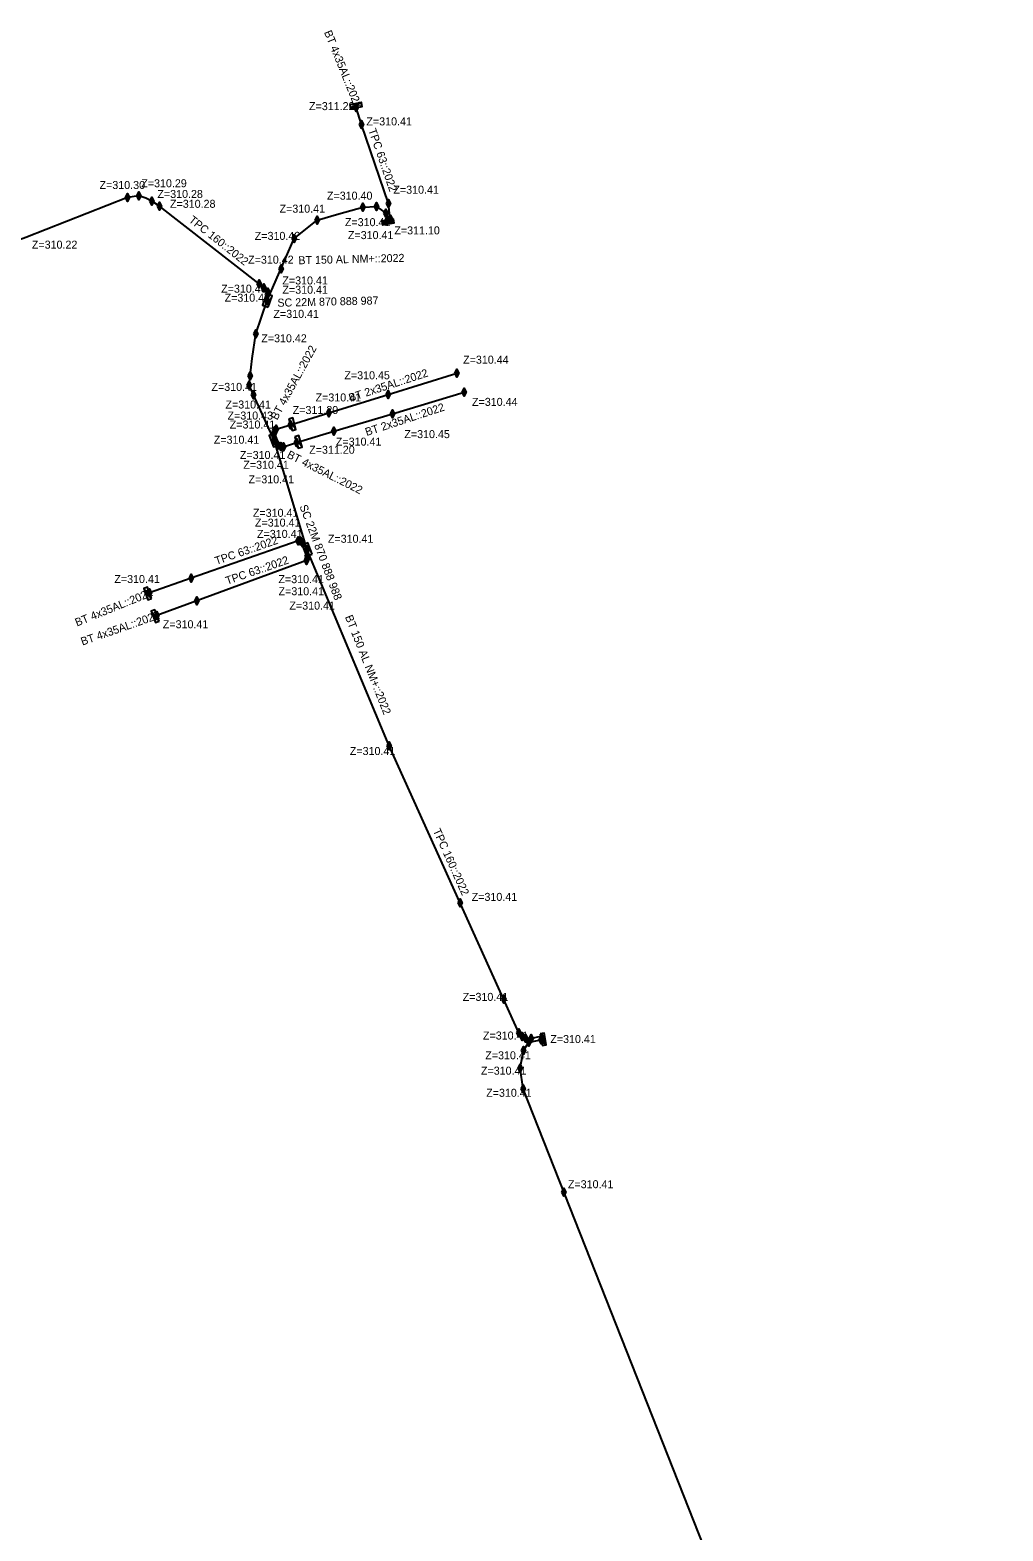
# Model space of a CAD drawing. Extents: x 799271 to 799523, y 67737 to 68184.
# Drawn here: x 799313.8 to 799362.5, y 68072.4 to 68147.5 of the extents above; entities that cross this region are included whole.
import ezdxf

# ---------------------------------------------------------------- set-up
doc = ezdxf.new("R2010")
doc.units = 0
for name, color, linetype in [('PGOC_BRCHT_DI_CONSTRUIT', 7, 'Continuous'), ('PGOC_BRCHT_LR_CONSTRUIT', 7, 'Continuous'), ('PGOC_BT_CONSTRUIT', 7, 'Continuous'), ('PGOC_PROTECTION_MECANIQUE', 7, 'Continuous'), ('PGOC_PTRL', 7, 'Continuous')]:
    doc.layers.add(name, color=color, linetype=linetype)

msp = doc.modelspace()

# ---------------------------------------------------------------- linework, layer by layer
at = {"layer": 'PGOC_BRCHT_DI_CONSTRUIT'}
for points in [[(799326.854, 68127.723), (799328.779, 68128.318), (799331.743, 68129.241), (799335.179, 68130.296)], [(799327.159, 68126.839), (799329.027, 68127.398), (799331.95, 68128.272), (799335.54, 68129.356)]]:
    msp.add_lwpolyline(points, dxfattribs=at)
at = {"layer": 'PGOC_BRCHT_LR_CONSTRUIT'}
for p, q in [((799330.406, 68143.831), (799329.852, 68143.524)), ((799327.127, 68127.487), (799326.774, 68128.012)), ((799327.432, 68126.604), (799327.078, 68127.128)), ((799319.514, 68119.534), (799319.912, 68119.042)), ((799319.886, 68118.399), (799320.284, 68117.908))]:
    msp.add_line(p, q, dxfattribs=at)
for points in [[(799329.852, 68143.524), (799330.442, 68143.634), (799330.406, 68143.831), (799329.816, 68143.721)], [(799326.774, 68128.012), (799326.935, 68127.434), (799327.127, 68127.487), (799326.966, 68128.065)], [(799326.285, 68126.724), (799326.074, 68127.286), (799325.793, 68127.18), (799326.004, 68126.619)], [(799327.078, 68127.128), (799327.24, 68126.55), (799327.432, 68126.604), (799327.271, 68127.182)], [(799327.934, 68121.252), (799327.723, 68121.814), (799327.442, 68121.709), (799327.653, 68121.147)], [(799319.912, 68119.042), (799319.701, 68119.604), (799319.514, 68119.534), (799319.725, 68118.972)], [(799320.284, 68117.908), (799320.073, 68118.47), (799319.886, 68118.399), (799320.097, 68117.838)]]:
    msp.add_lwpolyline(points, close=True, dxfattribs=at)
for points in [[(799331.841, 68137.991), (799331.755, 68138.791), (799330.407, 68142.737), (799330.147, 68143.579)], [(799326.041, 68126.947), (799326.038, 68127.28), (799326.064, 68127.423), (799326.142, 68127.5), (799326.854, 68127.723)], [(799326.041, 68126.947), (799326.228, 68126.708), (799326.37, 68126.638), (799326.503, 68126.627), (799327.159, 68126.839)], [(799327.69, 68121.475), (799327.457, 68121.825), (799327.332, 68121.914), (799327.237, 68121.913), (799326.855, 68121.78), (799321.897, 68120.052), (799319.807, 68119.323)], [(799327.69, 68121.475), (799327.693, 68121.162), (799327.695, 68121.014), (799327.658, 68120.945), (799322.168, 68118.923), (799320.179, 68118.189)]]:
    msp.add_lwpolyline(points, dxfattribs=at)
at = {"layer": 'PGOC_BT_CONSTRUIT'}
for points in [[(799325.695, 68133.935), (799325.714, 68134.244), (799325.72, 68134.356), (799325.523, 68134.562), (799325.287, 68134.766), (799320.298, 68138.654), (799319.918, 68138.897), (799319.629, 68139.051), (799319.267, 68139.164), (799318.707, 68139.081), (799313.619, 68137.078), (799309.462, 68135.566), (799303.767, 68133.234), (799297.376, 68130.329), (799292.64, 68128.222), (799285.412, 68124.768), (799279.22, 68121.838), (799276.144, 68120.348), (799271.55, 68118.005), (799271.55, 68118.005), (799271.55, 68118.005)], [(799339.366, 68097.137), (799338.895, 68097.044), (799338.6, 68097.061), (799338.444, 68097.136), (799338.277, 68097.326), (799331.797, 68111.675), (799327.69, 68121.475), (799326.041, 68126.947), (799325.012, 68129.216), (799324.793, 68129.699), (799324.844, 68130.165), (799324.94, 68131.043), (799325.13, 68132.267), (799325.695, 68133.935), (799327.046, 68137.031), (799328.195, 68137.96), (799329.277, 68138.271), (799330.475, 68138.607), (799331.153, 68138.638), (799331.618, 68138.305), (799331.714, 68137.967)], [(799331.477, 68137.821), (799331.988, 68137.916)], [(799331.521, 68137.91), (799331.55, 68137.753)], [(799331.619, 68137.929), (799331.649, 68137.771)], [(799331.717, 68137.947), (799331.747, 68137.79)], [(799331.816, 68137.965), (799331.845, 68137.808)], [(799331.914, 68137.984), (799331.943, 68137.826)], [(799362.485, 68037.029), (799361.95, 68037.023), (799361.114, 68037.015), (799360.807, 68037.092), (799360.472, 68037.497), (799357.336, 68045.17), (799355.021, 68050.739), (799353.254, 68056.515), (799351.046, 68062.246), (799349.101, 68067.639), (799338.488, 68094.517), (799338.336, 68095.563), (799338.503, 68096.44), (799338.776, 68096.853), (799339.395, 68096.978)], [(799339.378, 68097.178), (799339.536, 68097.207)], [(799339.397, 68097.08), (799339.554, 68097.109)], [(799339.415, 68096.981), (799339.572, 68097.011)], [(799339.541, 68096.74), (799339.446, 68097.252)], [(799339.433, 68096.883), (799339.591, 68096.912)], [(799339.452, 68096.785), (799339.609, 68096.814)]]:
    msp.add_lwpolyline(points, dxfattribs=at)
for points in [[(799332.009, 68138.022), (799331.419, 68137.911), (799331.456, 68137.715), (799332.045, 68137.825)], [(799325.738, 68133.608), (799325.938, 68134.174), (799325.655, 68134.274), (799325.455, 68133.708)], [(799339.34, 68097.273), (799339.45, 68096.683), (799339.647, 68096.719), (799339.537, 68097.309)]]:
    msp.add_lwpolyline(points, close=True, dxfattribs=at)
at = {"layer": 'PGOC_PTRL'}
for points in [[(799330.047, 68143.579), (799330.147, 68143.779), (799330.247, 68143.579), (799330.147, 68143.379), (799330.047, 68143.579)], [(799330.247, 68143.579), (799330.147, 68143.579), (799330.047, 68143.579)], [(799330.147, 68143.779), (799330.147, 68143.379)], [(799330.307, 68142.737), (799330.407, 68142.937), (799330.507, 68142.737), (799330.407, 68142.537), (799330.307, 68142.737)], [(799330.507, 68142.737), (799330.407, 68142.737), (799330.307, 68142.737)], [(799330.407, 68142.937), (799330.407, 68142.537)], [(799318.607, 68139.081), (799318.707, 68139.281), (799318.807, 68139.081), (799318.707, 68138.881), (799318.607, 68139.081)], [(799318.807, 68139.081), (799318.707, 68139.081), (799318.607, 68139.081)], [(799318.707, 68139.281), (799318.707, 68138.881)], [(799319.167, 68139.164), (799319.267, 68139.364), (799319.367, 68139.164), (799319.267, 68138.964), (799319.167, 68139.164)], [(799319.367, 68139.164), (799319.267, 68139.164), (799319.167, 68139.164)], [(799319.267, 68139.364), (799319.267, 68138.964)], [(799319.818, 68138.897), (799319.918, 68139.097), (799320.018, 68138.897), (799319.918, 68138.697), (799319.818, 68138.897)], [(799319.918, 68139.097), (799319.918, 68138.697)], [(799331.655, 68138.791), (799331.755, 68138.991), (799331.855, 68138.791), (799331.755, 68138.591), (799331.655, 68138.791)], [(799331.755, 68138.991), (799331.755, 68138.591)], [(799320.018, 68138.897), (799319.918, 68138.897), (799319.818, 68138.897)], [(799320.198, 68138.654), (799320.298, 68138.854), (799320.398, 68138.654), (799320.298, 68138.454), (799320.198, 68138.654)], [(799320.398, 68138.654), (799320.298, 68138.654), (799320.198, 68138.654)], [(799320.298, 68138.854), (799320.298, 68138.454)], [(799330.375, 68138.607), (799330.475, 68138.807), (799330.575, 68138.607), (799330.475, 68138.407), (799330.375, 68138.607)], [(799330.575, 68138.607), (799330.475, 68138.607), (799330.375, 68138.607)], [(799330.475, 68138.807), (799330.475, 68138.407)], [(799331.053, 68138.638), (799331.153, 68138.838), (799331.253, 68138.638), (799331.153, 68138.438), (799331.053, 68138.638)], [(799331.253, 68138.638), (799331.153, 68138.638), (799331.053, 68138.638)], [(799331.153, 68138.838), (799331.153, 68138.438)], [(799331.518, 68138.305), (799331.618, 68138.505), (799331.718, 68138.305), (799331.618, 68138.105), (799331.518, 68138.305)], [(799331.718, 68138.305), (799331.618, 68138.305), (799331.518, 68138.305)], [(799331.618, 68138.505), (799331.618, 68138.105)], [(799331.855, 68138.791), (799331.755, 68138.791), (799331.655, 68138.791)], [(799328.095, 68137.96), (799328.195, 68138.16), (799328.295, 68137.96), (799328.195, 68137.76), (799328.095, 68137.96)], [(799328.295, 68137.96), (799328.195, 68137.96), (799328.095, 68137.96)], [(799328.195, 68138.16), (799328.195, 68137.76)], [(799331.614, 68137.967), (799331.714, 68138.167), (799331.814, 68137.967), (799331.714, 68137.767), (799331.614, 68137.967)], [(799331.814, 68137.967), (799331.714, 68137.967), (799331.614, 68137.967)], [(799331.714, 68138.167), (799331.714, 68137.767)], [(799331.749, 68137.999), (799331.849, 68138.199), (799331.949, 68137.999), (799331.849, 68137.799), (799331.749, 68137.999)], [(799331.949, 68137.999), (799331.849, 68137.999), (799331.749, 68137.999)], [(799331.849, 68138.199), (799331.849, 68137.799)], [(799326.946, 68137.031), (799327.046, 68137.231), (799327.146, 68137.031), (799327.046, 68136.831), (799326.946, 68137.031)], [(799327.146, 68137.031), (799327.046, 68137.031), (799326.946, 68137.031)], [(799327.046, 68137.231), (799327.046, 68136.831)], [(799326.287, 68135.522), (799326.387, 68135.722), (799326.487, 68135.522), (799326.387, 68135.322), (799326.287, 68135.522)], [(799326.487, 68135.522), (799326.387, 68135.522), (799326.287, 68135.522)], [(799326.387, 68135.722), (799326.387, 68135.322)], [(799325.187, 68134.766), (799325.287, 68134.966), (799325.387, 68134.766), (799325.287, 68134.566), (799325.187, 68134.766)], [(799325.387, 68134.766), (799325.287, 68134.766), (799325.187, 68134.766)], [(799325.287, 68134.966), (799325.287, 68134.566)], [(799325.423, 68134.562), (799325.523, 68134.762), (799325.623, 68134.562), (799325.523, 68134.362), (799325.423, 68134.562)], [(799325.623, 68134.562), (799325.523, 68134.562), (799325.423, 68134.562)], [(799325.523, 68134.762), (799325.523, 68134.362)], [(799325.62, 68134.356), (799325.72, 68134.556), (799325.82, 68134.356), (799325.72, 68134.156), (799325.62, 68134.356)], [(799325.72, 68134.556), (799325.72, 68134.156)], [(799325.595, 68133.935), (799325.695, 68134.135), (799325.795, 68133.935), (799325.695, 68133.735), (799325.595, 68133.935)], [(799325.795, 68133.935), (799325.695, 68133.935), (799325.595, 68133.935)], [(799325.614, 68134.244), (799325.714, 68134.444), (799325.814, 68134.244), (799325.714, 68134.044), (799325.614, 68134.244)], [(799325.814, 68134.244), (799325.714, 68134.244), (799325.614, 68134.244)], [(799325.82, 68134.356), (799325.72, 68134.356), (799325.62, 68134.356)], [(799325.695, 68134.135), (799325.695, 68133.735)], [(799325.714, 68134.444), (799325.714, 68134.044)], [(799325.03, 68132.267), (799325.13, 68132.467), (799325.23, 68132.267), (799325.13, 68132.067), (799325.03, 68132.267)], [(799325.23, 68132.267), (799325.13, 68132.267), (799325.03, 68132.267)], [(799325.13, 68132.467), (799325.13, 68132.067)], [(799324.744, 68130.165), (799324.844, 68130.365), (799324.944, 68130.165), (799324.844, 68129.965), (799324.744, 68130.165)], [(799324.944, 68130.165), (799324.844, 68130.165), (799324.744, 68130.165)], [(799324.844, 68130.365), (799324.844, 68129.965)], [(799335.079, 68130.296), (799335.179, 68130.496), (799335.279, 68130.296), (799335.179, 68130.096), (799335.079, 68130.296)], [(799335.279, 68130.296), (799335.179, 68130.296), (799335.079, 68130.296)], [(799335.179, 68130.496), (799335.179, 68130.096)], [(799324.693, 68129.699), (799324.793, 68129.899), (799324.893, 68129.699), (799324.793, 68129.499), (799324.693, 68129.699)], [(799324.893, 68129.699), (799324.793, 68129.699), (799324.693, 68129.699)], [(799324.793, 68129.899), (799324.793, 68129.499)], [(799324.912, 68129.216), (799325.012, 68129.416), (799325.112, 68129.216), (799325.012, 68129.016), (799324.912, 68129.216)], [(799325.112, 68129.216), (799325.012, 68129.216), (799324.912, 68129.216)], [(799325.012, 68129.416), (799325.012, 68129.016)], [(799331.643, 68129.241), (799331.743, 68129.441), (799331.843, 68129.241), (799331.743, 68129.041), (799331.643, 68129.241)], [(799331.843, 68129.241), (799331.743, 68129.241), (799331.643, 68129.241)], [(799331.743, 68129.441), (799331.743, 68129.041)], [(799335.44, 68129.356), (799335.54, 68129.556), (799335.64, 68129.356), (799335.54, 68129.156), (799335.44, 68129.356)], [(799335.64, 68129.356), (799335.54, 68129.356), (799335.44, 68129.356)], [(799335.54, 68129.556), (799335.54, 68129.156)], [(799328.679, 68128.318), (799328.779, 68128.518), (799328.879, 68128.318), (799328.779, 68128.118), (799328.679, 68128.318)], [(799328.779, 68128.518), (799328.779, 68128.118)], [(799331.85, 68128.272), (799331.95, 68128.472), (799332.05, 68128.272), (799331.95, 68128.072), (799331.85, 68128.272)], [(799331.95, 68128.472), (799331.95, 68128.072)], [(799326.042, 68127.5), (799326.142, 68127.7), (799326.242, 68127.5), (799326.142, 68127.3), (799326.042, 68127.5)], [(799326.142, 68127.7), (799326.142, 68127.3)], [(799326.754, 68127.723), (799326.854, 68127.923), (799326.954, 68127.723), (799326.854, 68127.523), (799326.754, 68127.723)], [(799326.954, 68127.723), (799326.854, 68127.723), (799326.754, 68127.723)], [(799326.854, 68127.923), (799326.854, 68127.523)], [(799328.879, 68128.318), (799328.779, 68128.318), (799328.679, 68128.318)], [(799332.05, 68128.272), (799331.95, 68128.272), (799331.85, 68128.272)], [(799325.938, 68127.28), (799326.038, 68127.48), (799326.138, 68127.28), (799326.038, 68127.08), (799325.938, 68127.28)], [(799326.138, 68127.28), (799326.038, 68127.28), (799325.938, 68127.28)], [(799325.941, 68126.947), (799326.041, 68127.147), (799326.141, 68126.947), (799326.041, 68126.747), (799325.941, 68126.947)], [(799325.964, 68127.423), (799326.064, 68127.623), (799326.164, 68127.423), (799326.064, 68127.223), (799325.964, 68127.423)], [(799326.164, 68127.423), (799326.064, 68127.423), (799325.964, 68127.423)], [(799326.038, 68127.48), (799326.038, 68127.08)], [(799326.041, 68127.147), (799326.041, 68126.747)], [(799326.242, 68127.5), (799326.142, 68127.5), (799326.042, 68127.5)], [(799326.064, 68127.623), (799326.064, 68127.223)], [(799327.059, 68126.839), (799327.159, 68127.039), (799327.259, 68126.839), (799327.159, 68126.639), (799327.059, 68126.839)], [(799327.159, 68127.039), (799327.159, 68126.639)], [(799328.927, 68127.398), (799329.027, 68127.598), (799329.127, 68127.398), (799329.027, 68127.198), (799328.927, 68127.398)], [(799329.127, 68127.398), (799329.027, 68127.398), (799328.927, 68127.398)], [(799329.027, 68127.598), (799329.027, 68127.198)], [(799326.141, 68126.947), (799326.041, 68126.947), (799325.941, 68126.947)], [(799326.128, 68126.708), (799326.228, 68126.908), (799326.328, 68126.708), (799326.228, 68126.508), (799326.128, 68126.708)], [(799326.328, 68126.708), (799326.228, 68126.708), (799326.128, 68126.708)], [(799326.228, 68126.908), (799326.228, 68126.508)], [(799326.27, 68126.638), (799326.37, 68126.838), (799326.47, 68126.638), (799326.37, 68126.438), (799326.27, 68126.638)], [(799326.47, 68126.638), (799326.37, 68126.638), (799326.27, 68126.638)], [(799326.37, 68126.838), (799326.37, 68126.438)], [(799326.403, 68126.627), (799326.503, 68126.827), (799326.603, 68126.627), (799326.503, 68126.427), (799326.403, 68126.627)], [(799326.603, 68126.627), (799326.503, 68126.627), (799326.403, 68126.627)], [(799326.503, 68126.827), (799326.503, 68126.427)], [(799327.259, 68126.839), (799327.159, 68126.839), (799327.059, 68126.839)], [(799327.137, 68121.913), (799327.237, 68122.113), (799327.337, 68121.913), (799327.237, 68121.713), (799327.137, 68121.913)], [(799327.337, 68121.913), (799327.237, 68121.913), (799327.137, 68121.913)], [(799327.232, 68121.914), (799327.332, 68122.114), (799327.432, 68121.914), (799327.332, 68121.714), (799327.232, 68121.914)], [(799327.432, 68121.914), (799327.332, 68121.914), (799327.232, 68121.914)], [(799327.237, 68122.113), (799327.237, 68121.713)], [(799327.332, 68122.114), (799327.332, 68121.714)], [(799327.357, 68121.825), (799327.457, 68122.025), (799327.557, 68121.825), (799327.457, 68121.625), (799327.357, 68121.825)], [(799327.557, 68121.825), (799327.457, 68121.825), (799327.357, 68121.825)], [(799327.457, 68122.025), (799327.457, 68121.625)], [(799327.558, 68120.945), (799327.658, 68121.145), (799327.758, 68120.945), (799327.658, 68120.745), (799327.558, 68120.945)], [(799327.59, 68121.475), (799327.69, 68121.675), (799327.79, 68121.475), (799327.69, 68121.275), (799327.59, 68121.475)], [(799327.79, 68121.475), (799327.69, 68121.475), (799327.59, 68121.475)], [(799327.593, 68121.162), (799327.693, 68121.362), (799327.793, 68121.162), (799327.693, 68120.962), (799327.593, 68121.162)], [(799327.793, 68121.162), (799327.693, 68121.162), (799327.593, 68121.162)], [(799327.595, 68121.014), (799327.695, 68121.214), (799327.795, 68121.014), (799327.695, 68120.814), (799327.595, 68121.014)], [(799327.795, 68121.014), (799327.695, 68121.014), (799327.595, 68121.014)], [(799327.658, 68121.145), (799327.658, 68120.745)], [(799327.69, 68121.675), (799327.69, 68121.275)], [(799327.693, 68121.362), (799327.693, 68120.962)], [(799327.695, 68121.214), (799327.695, 68120.814)], [(799321.797, 68120.052), (799321.897, 68120.252), (799321.997, 68120.052), (799321.897, 68119.852), (799321.797, 68120.052)], [(799321.897, 68120.252), (799321.897, 68119.852)], [(799327.758, 68120.945), (799327.658, 68120.945), (799327.558, 68120.945)], [(799319.707, 68119.323), (799319.807, 68119.523), (799319.907, 68119.323), (799319.807, 68119.123), (799319.707, 68119.323)], [(799319.807, 68119.523), (799319.807, 68119.123)], [(799321.997, 68120.052), (799321.897, 68120.052), (799321.797, 68120.052)], [(799319.907, 68119.323), (799319.807, 68119.323), (799319.707, 68119.323)], [(799322.068, 68118.923), (799322.168, 68119.123), (799322.268, 68118.923), (799322.168, 68118.723), (799322.068, 68118.923)], [(799322.268, 68118.923), (799322.168, 68118.923), (799322.068, 68118.923)], [(799322.168, 68119.123), (799322.168, 68118.723)], [(799320.079, 68118.189), (799320.179, 68118.389), (799320.279, 68118.189), (799320.179, 68117.989), (799320.079, 68118.189)], [(799320.279, 68118.189), (799320.179, 68118.189), (799320.079, 68118.189)], [(799320.179, 68118.389), (799320.179, 68117.989)], [(799331.697, 68111.675), (799331.797, 68111.875), (799331.897, 68111.675), (799331.797, 68111.475), (799331.697, 68111.675)], [(799331.897, 68111.675), (799331.797, 68111.675), (799331.697, 68111.675)], [(799331.797, 68111.875), (799331.797, 68111.475)], [(799335.24, 68103.831), (799335.34, 68104.031), (799335.44, 68103.831), (799335.34, 68103.631), (799335.24, 68103.831)], [(799335.44, 68103.831), (799335.34, 68103.831), (799335.24, 68103.831)], [(799335.34, 68104.031), (799335.34, 68103.631)], [(799337.419, 68099.005), (799337.519, 68099.205), (799337.619, 68099.005), (799337.519, 68098.805), (799337.419, 68099.005)], [(799337.519, 68099.205), (799337.519, 68098.805)], [(799337.619, 68099.005), (799337.519, 68099.005), (799337.419, 68099.005)], [(799338.177, 68097.326), (799338.277, 68097.526), (799338.377, 68097.326), (799338.277, 68097.126), (799338.177, 68097.326)], [(799338.377, 68097.326), (799338.277, 68097.326), (799338.177, 68097.326)], [(799338.277, 68097.526), (799338.277, 68097.126)], [(799338.344, 68097.136), (799338.444, 68097.336), (799338.544, 68097.136), (799338.444, 68096.936), (799338.344, 68097.136)], [(799338.544, 68097.136), (799338.444, 68097.136), (799338.344, 68097.136)], [(799338.444, 68097.336), (799338.444, 68096.936)], [(799338.5, 68097.061), (799338.6, 68097.261), (799338.7, 68097.061), (799338.6, 68096.861), (799338.5, 68097.061)], [(799338.7, 68097.061), (799338.6, 68097.061), (799338.5, 68097.061)], [(799338.6, 68097.261), (799338.6, 68096.861)], [(799338.676, 68096.853), (799338.776, 68097.053), (799338.876, 68096.853), (799338.776, 68096.653), (799338.676, 68096.853)], [(799338.776, 68097.053), (799338.776, 68096.653)], [(799338.795, 68097.044), (799338.895, 68097.244), (799338.995, 68097.044), (799338.895, 68096.844), (799338.795, 68097.044)], [(799338.995, 68097.044), (799338.895, 68097.044), (799338.795, 68097.044)], [(799338.895, 68097.244), (799338.895, 68096.844)], [(799339.295, 68096.978), (799339.395, 68097.178), (799339.495, 68096.978), (799339.395, 68096.778), (799339.295, 68096.978)], [(799339.495, 68096.978), (799339.395, 68096.978), (799339.295, 68096.978)], [(799339.395, 68097.178), (799339.395, 68096.778)], [(799338.403, 68096.44), (799338.503, 68096.64), (799338.603, 68096.44), (799338.503, 68096.24), (799338.403, 68096.44)], [(799338.603, 68096.44), (799338.503, 68096.44), (799338.403, 68096.44)], [(799338.503, 68096.64), (799338.503, 68096.24)], [(799338.876, 68096.853), (799338.776, 68096.853), (799338.676, 68096.853)], [(799338.236, 68095.563), (799338.336, 68095.763), (799338.436, 68095.563), (799338.336, 68095.363), (799338.236, 68095.563)], [(799338.436, 68095.563), (799338.336, 68095.563), (799338.236, 68095.563)], [(799338.336, 68095.763), (799338.336, 68095.363)], [(799338.388, 68094.517), (799338.488, 68094.717), (799338.588, 68094.517), (799338.488, 68094.317), (799338.388, 68094.517)], [(799338.488, 68094.717), (799338.488, 68094.317)], [(799338.588, 68094.517), (799338.488, 68094.517), (799338.388, 68094.517)], [(799340.426, 68089.355), (799340.526, 68089.555), (799340.626, 68089.355), (799340.526, 68089.155), (799340.426, 68089.355)], [(799340.526, 68089.555), (799340.526, 68089.155)], [(799340.626, 68089.355), (799340.526, 68089.355), (799340.426, 68089.355)]]:
    msp.add_lwpolyline(points, dxfattribs=at)

# ---------------------------------------------------------------- texts
at = {"layer": 'PGOC_BRCHT_DI_CONSTRUIT'}
for p in [(799329.842, 68128.868), (799330.665, 68127.159)]:
    msp.add_text('BT 2x35AL::2022', height=0.4, rotation=18.10154, dxfattribs=at).set_placement(p)
at = {"layer": 'PGOC_BRCHT_LR_CONSTRUIT'}
for s, rotation, p in [('BT 4x35AL::2022', 61.19009, (799326.186, 68127.928)), ('BT 4x35AL::2022', 333.22376, (799326.642, 68126.103)), ('SC 22M 870 888 988', 290.57469, (799327.299, 68123.647))]:
    msp.add_text(s, height=0.4, rotation=rotation, dxfattribs=at).set_placement(p)
at = {"layer": 'PGOC_BT_CONSTRUIT'}
for s, rotation, p in [('BT 4x35AL::2022', 292.06994, (799328.525, 68147.349)), ('BT 150 AL NM+::2022', 1.35034, (799327.253, 68135.746)), ('SC 22M 870 888 987', 1.35034, (799326.205, 68133.624)), ('BT 4x35AL::2022', 22.06994, (799316.177, 68117.634)), ('BT 4x35AL::2022', 19.25062, (799316.45, 68116.683)), ('BT 150 AL NM+::2022', 291.59842, (799329.573, 68118.122))]:
    msp.add_text(s, height=0.4, rotation=rotation, dxfattribs=at).set_placement(p)
at = {"layer": 'PGOC_PROTECTION_MECANIQUE'}
for s, rotation, p in [('TPC 63::2022', 289.09342, (799330.741, 68142.458)), ('TPC 160::2022', 321.58481, (799321.736, 68137.897)), ('TPC 63::2022', 19.09342, (799323.149, 68120.713)), ('TPC 63::2022', 19.09342, (799323.688, 68119.722)), ('TPC 160::2022', 294.17423, (799333.972, 68107.43))]:
    msp.add_text(s, height=0.4, rotation=rotation, dxfattribs=at).set_placement(p)
at = {"layer": 'PGOC_PTRL'}
for s, p in [('Z=311.22', (799327.782, 68143.454)), ('Z=310.41', (799330.652, 68142.691)), ('Z=310.30', (799317.306, 68139.511)), ('Z=310.29', (799319.394, 68139.598)), ('Z=310.28', (799320.199, 68139.062)), ('Z=310.28', (799320.83, 68138.571)), ('Z=310.40', (799328.678, 68138.978)), ('Z=310.41', (799332.001, 68139.275)), ('Z=310.41', (799326.309, 68138.328)), ('Z=310.41', (799329.576, 68137.653)), ('Z=311.10', (799332.048, 68137.242)), ('Z=310.22', (799313.923, 68136.529)), ('Z=310.42', (799325.069, 68136.968)), ('Z=310.41', (799329.727, 68137.007)), ('Z=310.42', (799324.737, 68135.778)), ('Z=310.40', (799323.388, 68134.327)), ('Z=310.41', (799326.448, 68134.738)), ('Z=310.41', (799326.452, 68134.276)), ('Z=310.41', (799323.56, 68133.876)), ('Z=310.41', (799326.003, 68133.069)), ('Z=310.42', (799325.395, 68131.847)), ('Z=310.44', (799335.488, 68130.778)), ('Z=310.45', (799329.55, 68129.998)), ('Z=310.41', (799322.903, 68129.418)), ('Z=310.41', (799328.109, 68128.89)), ('Z=310.41', (799323.603, 68128.536)), ('Z=311.20', (799326.966, 68128.261)), ('Z=310.44', (799335.932, 68128.669)), ('Z=310.43', (799323.707, 68127.985)), ('Z=310.41', (799323.819, 68127.537)), ('Z=310.41', (799323.02, 68126.777)), ('Z=310.41', (799329.125, 68126.681)), ('Z=310.45', (799332.548, 68127.056)), ('Z=310.41', (799324.325, 68126.013)), ('Z=311.20', (799327.791, 68126.275)), ('Z=310.41', (799324.496, 68125.524)), ('Z=310.41', (799324.757, 68124.796)), ('Z=310.41', (799324.975, 68123.121)), ('Z=310.41', (799325.078, 68122.632)), ('Z=310.41', (799325.181, 68122.067)), ('Z=310.41', (799328.726, 68121.825)), ('Z=310.41', (799318.046, 68119.812)), ('Z=310.41', (799326.252, 68119.805)), ('Z=310.41', (799326.258, 68119.201)), ('Z=310.41', (799326.802, 68118.483)), ('Z=310.41', (799320.471, 68117.551)), ('Z=310.41', (799329.822, 68111.212)), ('Z=310.41', (799335.916, 68103.921)), ('Z=310.41', (799335.467, 68098.922)), ('Z=310.41', (799336.48, 68096.99)), ('Z=310.41', (799339.847, 68096.813)), ('Z=310.41', (799336.596, 68096.001)), ('Z=310.41', (799336.379, 68095.233)), ('Z=310.41', (799336.641, 68094.126)), ('Z=310.41', (799340.728, 68089.555))]:
    msp.add_text(s, height=0.4, dxfattribs=at).set_placement(p)

doc.saveas('drawing.dxf')
